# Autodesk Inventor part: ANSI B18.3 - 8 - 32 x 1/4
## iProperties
IsCustomPart: 0
Created: 2007-03
Part Number: ANSI B18.3 - 8 - 32 x 1/4
Material: Steel, Mild
Description: Hexagon Socket Button Head Cap Screw
Document SubType Name: Modeling
Standard: ANSI B18.3
Standard Revision: 2003
Standards Organization: ANSI
Language: en-US
Size Designation: 8 - 32 x 1/4
Categories: <MemberInstance><Categories><Category DisplayName="Fasteners" InternalName="e4da775c-781d-43d5-af7c-5136215cf5a6" Mnemonic="FSTN"><Category DisplayName="Bolts"
Density: 1 g/cm^3
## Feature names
1. Body [Revolution]
2. Slot [Extrusion]
3. Fillet1
4. Chamfer1
5. Fillet2
